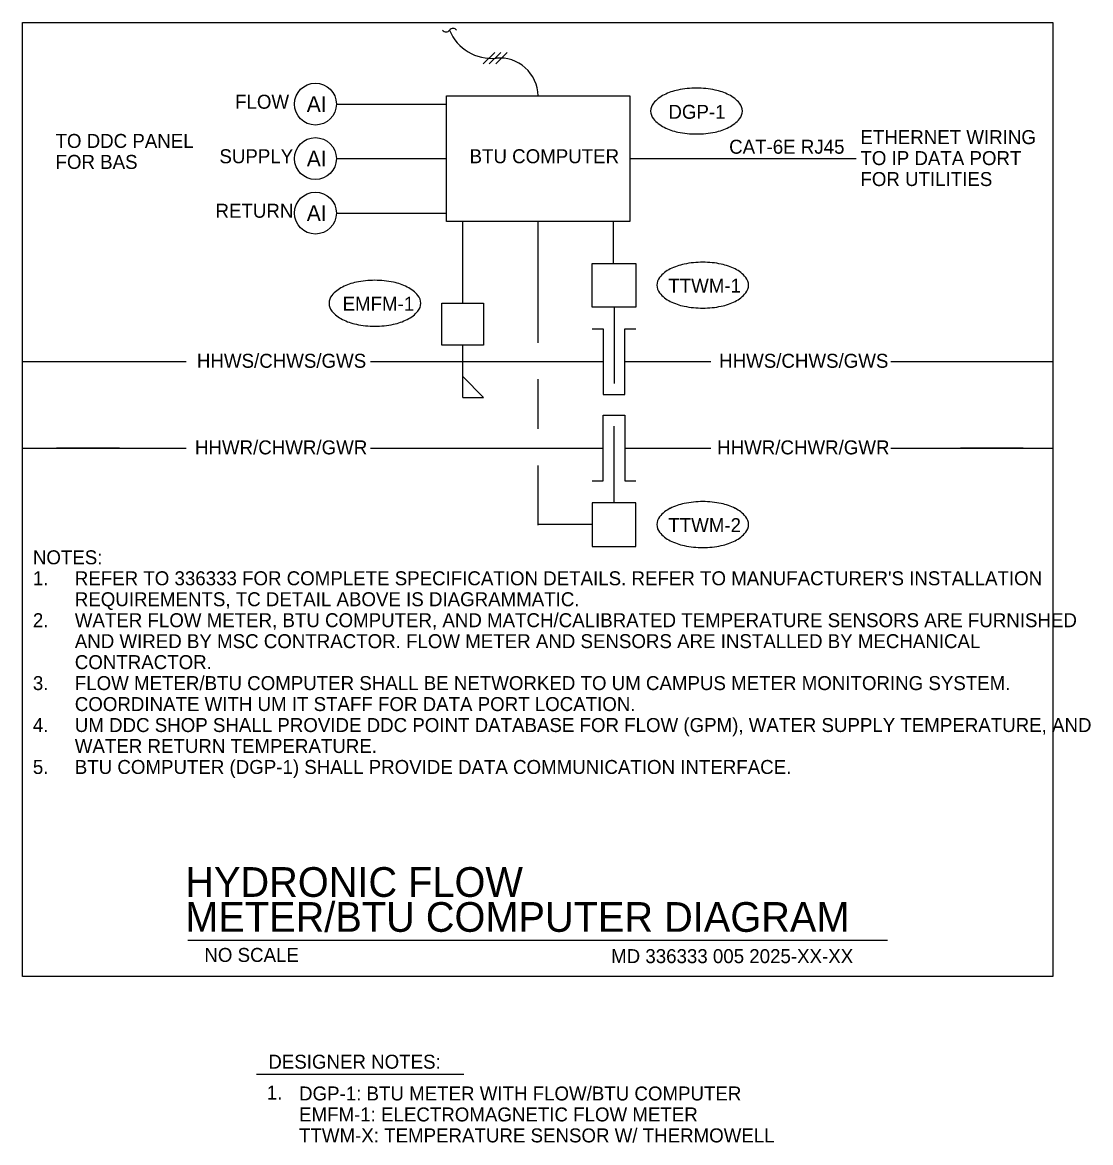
# Model space of a CAD drawing. Extents: x 10059.4 to 10110.4, y 10086 to 10139.5.
import ezdxf

# ---------------------------------------------------------------- set-up
doc = ezdxf.new("R2010")
doc.units = 0
doc.layers.add('G-DETL-GRID', color=7, linetype='Continuous')
doc.layers.add('G-DETL-LINE', color=7, linetype='Continuous')

# ---------------------------------------------------------------- blocks, each defined once
blk = doc.blocks.new('EL')
for centre, radius, start, end in [((0, -0.04669), 0.06232, 90, 101.70092), ((0, -0.04669), 0.06232, 78.29908, 90), ((-0.01206, -0.00902), 0.02244, 116.56505, 140.36073), ((-0.00479, -0.02357), 0.0387, 101.70092, 116.56505), ((0.00479, -0.02357), 0.0387, 63.43495, 78.29908), ((0.01206, -0.00902), 0.02244, 39.63927, 63.43495), ((-0.02295, 0), 0.0083, 140.36073, 180), ((-0.02295, 0), 0.0083, 180, 219.63927), ((0.02295, 0), 0.0083, 360, 39.63927), ((0.02295, 0), 0.0083, 320.36073, 360), ((-0.01206, 0.00902), 0.02244, 219.63927, 243.43495), ((0.01206, 0.00902), 0.02244, 296.56505, 320.36073), ((-0.00479, 0.02357), 0.0387, 243.43495, 258.29908), ((0, 0.04669), 0.06232, 258.29908, 270), ((0, 0.04669), 0.06232, 270, 281.70092), ((0.00479, 0.02357), 0.0387, 281.70092, 296.56505)]:
    blk.add_arc(centre, radius, start, end)
blk = doc.blocks.new('ARROW')
blk.add_line((-0.015625, 0), (0, 0))
blk = doc.blocks.new('TWELL')
for p, q in [((-0.00521, 0.04167), (-0.00521, 0.01042)), ((0.00521, 0.04167), (-0.00521, 0.04167)), ((0.00521, 0.01042), (0.00521, 0.04167)), ((0, 0), (0, 0.03646)), ((-0.00521, 0.01042), (-0.01042, 0.01042)), ((0.01042, 0.01042), (0.00521, 0.01042)), ((-0.01042, -0.02083), (-0.01042, 0)), ((-0.01042, 0), (0.01042, 0)), ((0.01042, 0), (0.01042, -0.02083)), ((0.01042, -0.02083), (-0.01042, -0.02083))]:
    blk.add_line(p, q)
blk = doc.blocks.new('AI')
blk.add_circle((0, 0), 0.01042)
blk.add_text('AI', height=0.007813).set_placement((-0.00428, -0.00391))

msp = doc.modelspace()

# ---------------------------------------------------------------- linework, layer by layer
for p, q in [((10067.294, 10095.691), (10100.663, 10095.691)), ((10070.571, 10089.309), (10080.457, 10089.309))]:
    msp.add_line(p, q)
at = {"layer": 'G-DETL-GRID'}
msp.add_lwpolyline([(10059.407, 10139.467), (10108.549, 10139.467), (10108.549, 10093.967), (10059.407, 10093.967)], close=True, dxfattribs=at)
at = {"layer": 'G-DETL-LINE'}
for p, q in [((10081.935, 10138.037), (10081.383, 10137.485)), ((10082.223, 10138.037), (10081.671, 10137.485)), ((10082.536, 10138.037), (10081.983, 10137.485)), ((10074.383, 10135.572), (10079.641, 10135.572)), ((10074.383, 10132.972), (10079.641, 10132.972)), ((10088.373, 10132.972), (10099.181, 10132.972)), ((10074.383, 10130.372), (10079.641, 10130.372)), ((10080.407, 10126.072), (10080.407, 10129.975)), ((10084.007, 10124.178), (10084.007, 10129.975)), ((10087.607, 10127.975), (10087.607, 10129.975)), ((10079.407, 10124.072), (10079.407, 10126.072)), ((10079.407, 10126.072), (10081.407, 10126.072)), ((10081.407, 10126.072), (10081.407, 10124.072)), ((10081.407, 10124.072), (10079.407, 10124.072)), ((10080.407, 10121.572), (10080.407, 10124.072)), ((10059.407, 10123.288), (10067.226, 10123.288)), ((10076.013, 10123.288), (10087.107, 10123.288)), ((10088.149, 10123.288), (10092.247, 10123.288)), ((10100.837, 10123.288), (10108.549, 10123.288)), ((10081.407, 10121.572), (10080.407, 10122.572)), ((10084.007, 10120.08), (10084.007, 10122.451)), ((10080.407, 10121.572), (10081.407, 10121.572)), ((10059.407, 10119.163), (10067.226, 10119.163)), ((10076.013, 10119.163), (10087.107, 10119.163)), ((10088.149, 10119.163), (10092.247, 10119.163)), ((10100.836, 10119.163), (10108.549, 10119.163)), ((10084.007, 10115.482), (10084.007, 10118.326)), ((10086.586, 10115.517), (10084.007, 10115.517))]:
    msp.add_line(p, q, dxfattribs=at)
msp.add_lwpolyline([(10079.641, 10135.969), (10088.373, 10135.969), (10088.373, 10129.975), (10079.641, 10129.975), (10079.641, 10135.969)], dxfattribs=at)
for centre, radius, start, end in [((10079.949, 10138.969), 0.208, 36.8699, 143.1301), ((10079.616, 10139.219), 0.208, 216.8699, 323.1301), ((10081.789, 10139.918), 2.169, 202.3267, 275.5981), ((10082.173, 10135.933), 1.834, 1.1088, 95.3936)]:
    msp.add_arc(centre, radius, start, end, dxfattribs=at)

# ---------------------------------------------------------------- block references
for name, p, xscale, yscale in [('AI', (10073.383, 10135.572), 96, 96), ('EL', (10091.56, 10135.239), 70, 70), ('AI', (10073.383, 10132.972), 96, 96), ('AI', (10073.383, 10130.372), 96, 96), ('EL', (10091.857, 10126.934), 70, 70), ('EL', (10076.22, 10126.072), 70, 70), ('ARROW', (10064.035, 10123.288), 192, 192), ('ARROW', (10107.148, 10123.288), 192, 192), ('EL', (10091.857, 10115.517), 70, 70)]:
    msp.add_blockref(name, p, dxfattribs=dict(at, xscale=xscale, yscale=yscale))
for name, p, xscale, yscale, rotation in [('TWELL', (10087.628, 10125.892), 100, 100, 180), ('TWELL', (10087.628, 10116.559), 100, -100, 180), ('ARROW', (10061.035, 10119.163), 192, 192, 179.99999999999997), ('ARROW', (10104.148, 10119.163), 192, 192, 179.99999999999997)]:
    msp.add_blockref(name, p, dxfattribs=dict(at, xscale=xscale, yscale=yscale, rotation=rotation))

# ---------------------------------------------------------------- texts
for s, height, p in [('HYDRONIC FLOW', 1.41667, (10067.177, 10097.759)), ('METER/BTU COMPUTER DIAGRAM', 1.41667, (10067.177, 10096.092)), ('NO SCALE', 0.6667, (10068.087, 10094.656)), ('DESIGNER NOTES:', 0.66667, (10071.137, 10089.563)), ('1.', 0.6667, (10071.064, 10088.092)), ('DGP-1: BTU METER WITH FLOW/BTU COMPUTER', 0.66667, (10072.602, 10088.048)), ('EMFM-1: ELECTROMAGNETIC FLOW METER', 0.66667, (10072.602, 10087.048)), ('TTWM-X: TEMPERATURE SENSOR W/ THERMOWELL', 0.66667, (10072.602, 10086.048))]:
    msp.add_text(s, height=height).set_placement(p)
for s, height, p in [('FLOW', 0.6667, (10069.552, 10135.35)), ('DGP-1', 0.6667, (10090.22, 10134.868)), ('ETHERNET WIRING ', 0.66667, (10099.379, 10133.662)), ('TO DDC PANEL ', 0.66667, (10060.987, 10133.48)), ('CAT-6E RJ45', 0.66667, (10093.118, 10133.203)), ('SUPPLY', 0.6667, (10068.804, 10132.75)), ('BTU COMPUTER', 0.66667, (10080.736, 10132.75)), ('TO IP DATA PORT ', 0.66667, (10099.379, 10132.662)), ('FOR BAS', 0.6667, (10060.987, 10132.48)), ('FOR UTILITIES', 0.66667, (10099.379, 10131.662)), ('RETURN', 0.6667, (10068.617, 10130.15)), ('TTWM-1', 0.6667, (10090.216, 10126.578)), ('EMFM-1', 0.6667, (10074.678, 10125.716)), ('HHWS/CHWS/GWS', 0.66667, (10067.732, 10122.993)), ('HHWS/CHWS/GWS', 0.66667, (10092.64, 10122.993)), ('HHWR/CHWR/GWR', 0.66667, (10067.638, 10118.864)), ('HHWR/CHWR/GWR', 0.66667, (10092.545, 10118.864)), ('TTWM-2', 0.6667, (10090.216, 10115.155)), ('NOTES:', 0.6667, (10059.907, 10113.621)), ('1.', 0.6667, (10059.907, 10112.621)), ("REFER TO 336333 FOR COMPLETE SPECIFICATION DETAILS. REFER TO MANUFACTURER'S INSTALLATION ", 0.66667, (10061.907, 10112.621)), ('REQUIREMENTS, TC DETAIL ABOVE IS DIAGRAMMATIC.', 0.66667, (10061.907, 10111.621)), ('WATER FLOW METER, BTU COMPUTER, AND MATCH/CALIBRATED TEMPERATURE SENSORS ARE FURNISHED ', 0.66667, (10061.907, 10110.621)), ('2.', 0.6667, (10059.907, 10110.621)), ('AND WIRED BY MSC CONTRACTOR. FLOW METER AND SENSORS ARE INSTALLED BY MECHANICAL ', 0.66667, (10061.907, 10109.621)), ('CONTRACTOR.', 0.66667, (10061.907, 10108.621)), ('3.', 0.6667, (10059.907, 10107.621)), ('FLOW METER/BTU COMPUTER SHALL BE NETWORKED TO UM CAMPUS METER MONITORING SYSTEM. ', 0.66667, (10061.907, 10107.621)), ('COORDINATE WITH UM IT STAFF FOR DATA PORT LOCATION.', 0.66667, (10061.907, 10106.621)), ('4.', 0.6667, (10059.907, 10105.621)), ('UM DDC SHOP SHALL PROVIDE DDC POINT DATABASE FOR FLOW (GPM), WATER SUPPLY TEMPERATURE, AND ', 0.66667, (10061.907, 10105.621)), ('WATER RETURN TEMPERATURE.', 0.66667, (10061.907, 10104.621)), ('5.', 0.6667, (10059.907, 10103.621)), ('BTU COMPUTER (DGP-1) SHALL PROVIDE DATA COMMUNICATION INTERFACE.', 0.66667, (10061.907, 10103.621)), ('MD 336333 005 2025-XX-XX', 0.66667, (10087.486, 10094.598))]:
    msp.add_text(s, height=height, dxfattribs=at).set_placement(p)

doc.saveas('drawing.dxf')
